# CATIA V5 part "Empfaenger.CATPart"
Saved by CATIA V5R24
Part number: Empfaenger
Bounding box of the stored display mesh (mm): x -19.255 to 19.255, y -16.675 to 16.675, z 29 to 65
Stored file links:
  D:\Test_mst_loeschen\Empfaenger.CATPart
  D:\Test_mst_loeschen\Var_Sketch_mit_Publikation.CATProduct
  \CATIA_V5_erledigtd Fragstellungen\Catpart_mit_Parametersketch\Var_Sketch_mit_Publikation.CATProduct
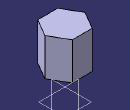
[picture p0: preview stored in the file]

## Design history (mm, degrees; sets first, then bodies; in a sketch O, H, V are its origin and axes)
Set1
  DatumCurve1 "Shape": linked copy from another document
Body1 (main body)
  Pad1: profile DatumCurve1, length 65, opposite side length -29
